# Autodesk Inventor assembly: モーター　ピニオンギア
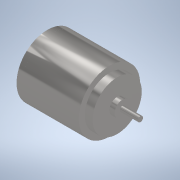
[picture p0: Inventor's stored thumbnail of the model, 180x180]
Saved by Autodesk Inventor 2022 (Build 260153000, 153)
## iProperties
Created: 2024-12
Part Number: モーター　ピニオンギア
Document SubType Name: Assembly
Designer: jsat7
Author: jsat7
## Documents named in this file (2)
- C:\Users\jsat7\OneDrive\デスクトップ\CAD 長田\モーター　ピニオンギア.iam
- C:\Users\jsat7\OneDrive\デスクトップ\卒論2024\３DCAD\ギアボックス\部品図\モーター.ipt
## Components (1 placed, 1 different names)
1. モーター:1
